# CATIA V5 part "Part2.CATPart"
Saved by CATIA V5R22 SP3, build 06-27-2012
Part number: Part2
Bounding box of the stored display mesh (mm): x -24.106 to 24.106, y -24.106 to 24.106, z 0 to 80
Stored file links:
  D:\Users\matejcekp\Downloads\Catia\Nová složka\Part2.CATPart
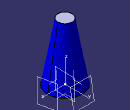
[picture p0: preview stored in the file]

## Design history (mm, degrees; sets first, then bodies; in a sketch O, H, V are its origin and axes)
AxisSystem1: origin (0, 0, 0), X (1, 0, 0), Y (0, 1, 0), Z (0, 0, 1)
Set1
  Extrude1: Lim1 27, Lim2 0, Direction edge [YZ plane of AxisSystem1 | XY plane of AxisSystem1], Element1 vertex [YZ plane of AxisSystem1 | ZX plane of AxisSystem1 | XY plane of AxisSystem1]
  Extract1: ExtractElem face of Pad1 from Sketch1.A1
  Intersect1: ToIntersect1 Extract1, ToIntersect2 Extrude1
  Plane1: type Tangent, Support face of Pad1 from Sketch1.A1, RefPoint vertex of Intersect1
  Plane2 "Plane.2": type Angle, RefPlane YZ plane of AxisSystem1, Direction edge [ZX plane of AxisSystem1 | YZ plane of AxisSystem1], Angle -1.7817
  Extrude2: Element1 vertex [YZ plane of AxisSystem1 | ZX plane of AxisSystem1 | XY plane of AxisSystem1], Lim1 27, Lim2 0, Direction Plane2
  Intersect2: ToIntersect1 Extract1, ToIntersect2 Extrude2
  Plane3 "Plane.3": type Tangent, Support face of Pad1 from Sketch1.A1, RefPoint vertex of Intersect2
Body1 (main body)
  Sketch1 on xy-plane, origin (0, 0, 0), H (1, 0, 0), V (0, 1, 0)
    circle A1 centre (0, 0) radius 10
    reference projected point E1 (0, 0) from vertex [YZ plane of AxisSystem1 | ZX plane of AxisSystem1 | XY plane of AxisSystem1]
    radius A1 = 10
    concentricity: E1 A1
  Pad1: profile Sketch1, direction (0, 0, 1), length 80
  Draft1: Angle 10, Neutral end face of Pad1, PullDir end face of Pad1, SupportToDraft face of Pad1 from Sketch1.A1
